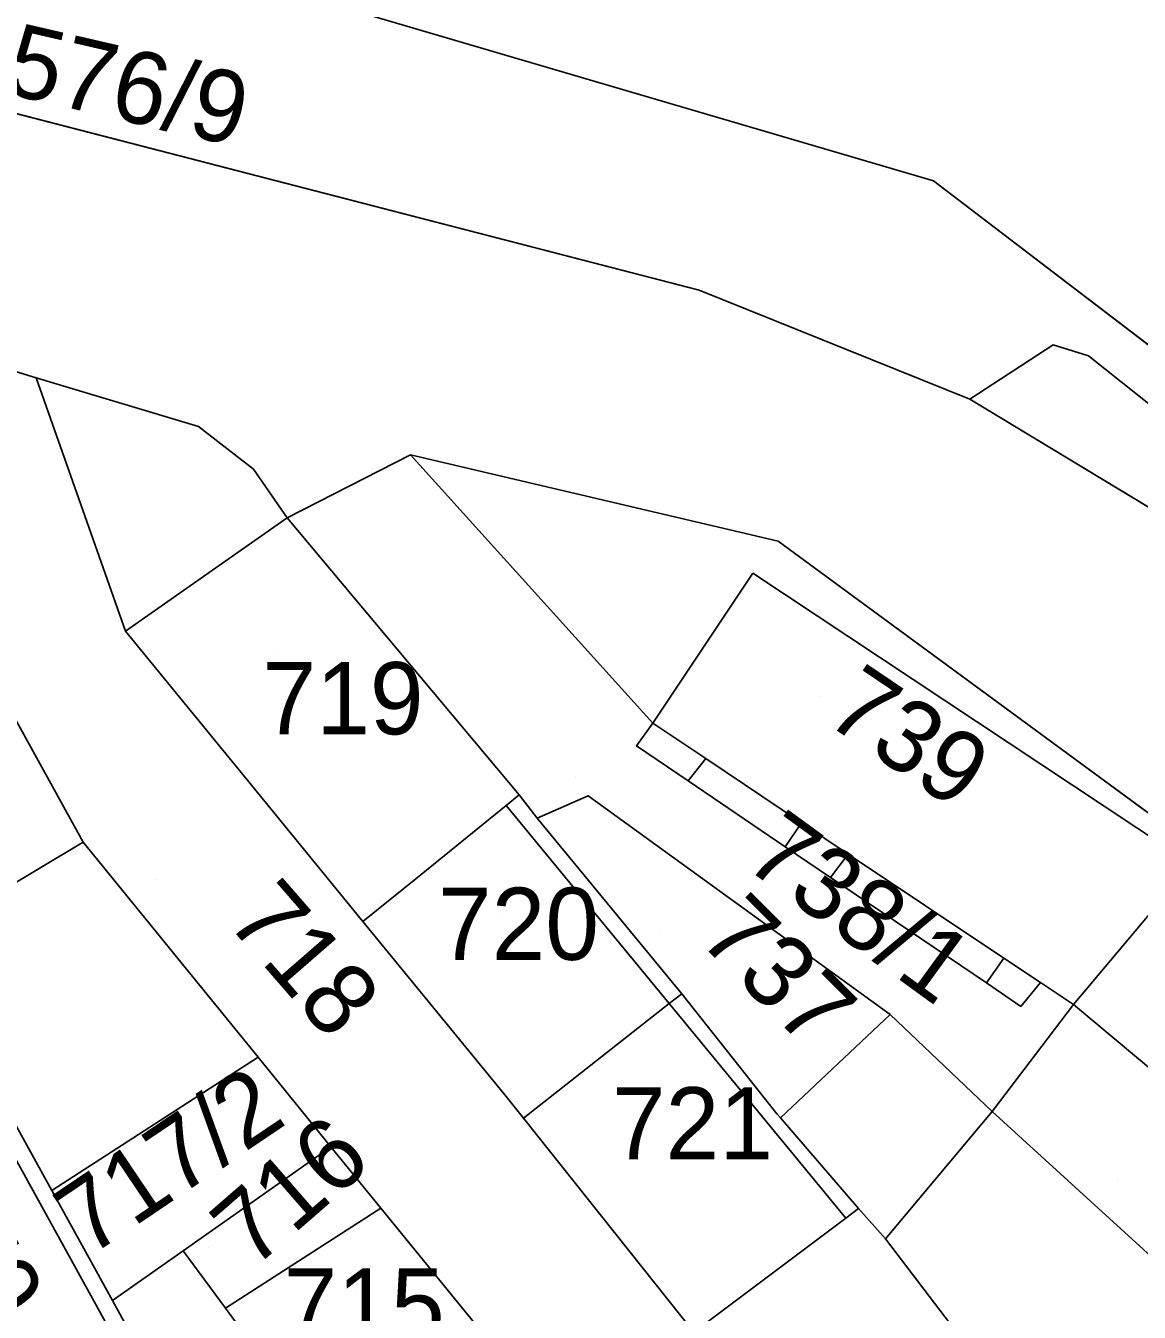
# Model space of a CAD drawing. Extents: x -263943 to -261149, y -1236934 to -1230686.
# Drawn here: x -262510.84 to -262479.98, y -1235394.91 to -1235359.25 of the extents above; entities that cross this region are included whole.
import ezdxf

# ---------------------------------------------------------------- set-up
doc = ezdxf.new("R2010")
doc.units = 0
for name, color, linetype in [('body_kn', 7, 'Continuous'), ('kladpar_druhypozemkov', 7, 'Continuous'), ('kladpar_hranice', 7, 'Continuous'), ('kladpar_parcelnecisla', 7, 'Continuous'), ('kladpar_plochy', 7, 'Continuous'), ('zappar_hrandruhpozemk', 7, 'Continuous')]:
    doc.layers.add(name, color=color, linetype=linetype)

msp = doc.modelspace()

# ---------------------------------------------------------------- linework, layer by layer
at = {"layer": 'body_kn'}
for p, q in [((-262485.69, -1235363.55), (-262485.69, -1235363.55)), ((-262492.18, -1235366.58), (-262492.18, -1235366.58)), ((-262482.37, -1235368.1), (-262482.37, -1235368.1)), ((-262481.39, -1235368.4), (-262481.39, -1235368.4)), ((-262510.56, -1235369.01), (-262510.56, -1235369.01)), ((-262510.56, -1235369.01), (-262510.56, -1235369.01)), ((-262484.68, -1235369.6), (-262484.68, -1235369.6)), ((-262484.68, -1235369.6), (-262484.68, -1235369.6)), ((-262506.06, -1235370.36), (-262506.06, -1235370.36)), ((-262500.18, -1235371.15), (-262500.18, -1235371.15)), ((-262504.53, -1235371.54), (-262504.53, -1235371.54)), ((-262503.6, -1235372.89), (-262503.6, -1235372.89)), ((-262503.6, -1235372.89), (-262503.6, -1235372.89)), ((-262489.99, -1235373.54), (-262489.99, -1235373.54)), ((-262490.69, -1235374.42), (-262490.69, -1235374.42)), ((-262508.08, -1235376.03), (-262508.08, -1235376.03)), ((-262493.47, -1235378.58), (-262493.47, -1235378.58)), ((-262493.47, -1235378.58), (-262493.47, -1235378.58)), ((-262493.92, -1235379.21), (-262493.92, -1235379.21)), ((-262492, -1235379.56), (-262492, -1235379.56)), ((-262504.79, -1235380.05), (-262504.79, -1235380.05)), ((-262492.49, -1235380.18), (-262492.49, -1235380.18)), ((-262492.49, -1235380.18), (-262492.49, -1235380.18)), ((-262497.17, -1235380.57), (-262497.17, -1235380.57)), ((-262497.17, -1235380.57), (-262497.17, -1235380.57)), ((-262495.26, -1235380.59), (-262495.26, -1235380.59)), ((-262497.53, -1235380.86), (-262497.53, -1235380.86)), ((-262497.53, -1235380.86), (-262497.53, -1235380.86)), ((-262496.67, -1235381.21), (-262496.67, -1235381.21)), ((-262489.35, -1235381.34), (-262489.35, -1235381.34)), ((-262509.25, -1235381.88), (-262509.25, -1235381.88)), ((-262489.8, -1235382.01), (-262489.8, -1235382.01)), ((-262489.8, -1235382.01), (-262489.8, -1235382.01)), ((-262488.05, -1235382.21), (-262488.05, -1235382.21)), ((-262500.03, -1235382.89), (-262500.03, -1235382.89)), ((-262488.54, -1235382.86), (-262488.54, -1235382.86)), ((-262488.54, -1235382.86), (-262488.54, -1235382.86)), ((-262501.5, -1235384.08), (-262501.5, -1235384.08)), ((-262483.74, -1235385.09), (-262483.74, -1235385.09)), ((-262484.22, -1235385.78), (-262484.22, -1235385.78)), ((-262484.22, -1235385.78), (-262484.22, -1235385.78)), ((-262482.72, -1235385.77), (-262482.72, -1235385.77)), ((-262492.66, -1235386.08), (-262492.66, -1235386.08)), ((-262492.66, -1235386.08), (-262492.66, -1235386.08)), ((-262493.01, -1235386.35), (-262493.01, -1235386.35)), ((-262493.01, -1235386.35), (-262493.01, -1235386.35)), ((-262486.89, -1235386.65), (-262486.89, -1235386.65)), ((-262483.27, -1235386.43), (-262483.27, -1235386.43)), ((-262481.81, -1235386.38), (-262481.81, -1235386.38)), ((-262481.81, -1235386.38), (-262481.81, -1235386.38)), ((-262504.4, -1235387.84), (-262504.4, -1235387.84)), ((-262504.4, -1235387.84), (-262504.4, -1235387.84)), ((-262497.57, -1235388.88), (-262497.57, -1235388.88)), ((-262497.05, -1235389.53), (-262497.05, -1235389.53)), ((-262490.03, -1235389.41), (-262490.03, -1235389.41)), ((-262489.93, -1235389.52), (-262489.93, -1235389.52)), ((-262489.93, -1235389.52), (-262489.93, -1235389.52)), ((-262484.06, -1235389.34), (-262484.06, -1235389.34)), ((-262502.39, -1235390.32), (-262502.39, -1235390.32)), ((-262510.12, -1235391.53), (-262510.12, -1235391.53)), ((-262510.12, -1235391.53), (-262510.12, -1235391.53)), ((-262501, -1235392.02), (-262501, -1235392.02)), ((-262487.77, -1235392.03), (-262487.77, -1235392.03)), ((-262487.77, -1235392.03), (-262487.77, -1235392.03)), ((-262488.12, -1235392.3), (-262488.12, -1235392.3)), ((-262487.02, -1235392.87), (-262487.02, -1235392.87)), ((-262506.48, -1235393.2), (-262506.48, -1235393.2)), ((-262506.48, -1235393.2), (-262506.48, -1235393.2)), ((-262508.44, -1235394.58), (-262508.44, -1235394.58)), ((-262508.44, -1235394.58), (-262508.44, -1235394.58)), ((-262505.31, -1235394.79), (-262505.31, -1235394.79)), ((-262505.31, -1235394.79), (-262505.31, -1235394.79))]:
    msp.add_line(p, q, dxfattribs=at)
at = {"layer": 'kladpar_druhypozemkov'}
for p, q in [((-262508.29, -1235360.29), (-262508.29, -1235360.29)), ((-262503.85, -1235376.55), (-262503.85, -1235376.55)), ((-262488.85, -1235377.83), (-262488.85, -1235377.83)), ((-262495.6, -1235380.08), (-262495.6, -1235380.08)), ((-262507.26, -1235382.9), (-262507.26, -1235382.9)), ((-262497.77, -1235383.86), (-262497.77, -1235383.86)), ((-262493.25, -1235384.33), (-262493.25, -1235384.33)), ((-262493.08, -1235389.24), (-262493.08, -1235389.24)), ((-262506.45, -1235389.76), (-262506.45, -1235389.76)), ((-262480.6, -1235391.23), (-262480.6, -1235391.23)), ((-262505.77, -1235393.11), (-262505.77, -1235393.11)), ((-262501.68, -1235394.37), (-262501.68, -1235394.37))]:
    msp.add_line(p, q, dxfattribs=at)
at = {"layer": 'kladpar_hranice'}
for points in [[(-262395.03, -1235450.14), (-262423.63, -1235423.11), (-262436.22, -1235407.42), (-262449.19, -1235391.42), (-262471.72, -1235374.22), (-262485.69, -1235363.55), (-262518.57, -1235353.89), (-262518.6, -1235353.56), (-262519.93, -1235347.59), (-262525.13, -1235332.75), (-262534.5, -1235316.26), (-262539.66, -1235305.8), (-262542.07, -1235301.69)], [(-262471.72, -1235374.22), (-262473.44, -1235374.61), (-262474.8, -1235376.29), (-262478.54, -1235373.32), (-262484.68, -1235369.6), (-262492.18, -1235366.58), (-262518.32, -1235359.83), (-262518.86, -1235358.75), (-262518.37, -1235355.88), (-262518.57, -1235353.89), (-262485.69, -1235363.55), (-262471.72, -1235374.22)], [(-262518.86, -1235358.75), (-262518.32, -1235359.83), (-262492.18, -1235366.58), (-262484.68, -1235369.6), (-262478.54, -1235373.32)], [(-262478.59, -1235381.91), (-262489.99, -1235373.54), (-262500.18, -1235371.15), (-262503.6, -1235372.89), (-262504.53, -1235371.54), (-262506.06, -1235370.36), (-262510.56, -1235369.01), (-262514.12, -1235367.92), (-262515.65, -1235366.4), (-262525.02, -1235364.84), (-262525.23, -1235364.81), (-262525.77, -1235364.71), (-262532.61, -1235363.38), (-262538.03, -1235363.56)], [(-262504.4, -1235387.84), (-262510.12, -1235391.53), (-262511.46, -1235389.1), (-262513.94, -1235384.68), (-262519.73, -1235374.38), (-262522.17, -1235370.05), (-262525.02, -1235364.84), (-262515.65, -1235366.4), (-262516.74, -1235367.01), (-262511.13, -1235377.14), (-262511.7, -1235377.45), (-262509.25, -1235381.88), (-262504.4, -1235387.84)], [(-262478.88, -1235424.54), (-262480.47, -1235421.95), (-262484.72, -1235415.05), (-262489.9, -1235406.87), (-262494.02, -1235400.6), (-262498.1, -1235395.58), (-262501, -1235392.02), (-262502.39, -1235390.32), (-262504.4, -1235387.84), (-262509.25, -1235381.88), (-262511.7, -1235377.45), (-262511.13, -1235377.14), (-262516.74, -1235367.01), (-262515.65, -1235366.4)], [(-262515.65, -1235366.4), (-262514.12, -1235367.92), (-262510.56, -1235369.01), (-262506.06, -1235370.36), (-262504.53, -1235371.54), (-262503.6, -1235372.89), (-262508.08, -1235376.03), (-262504.79, -1235380.05), (-262501.5, -1235384.08), (-262497.57, -1235388.88), (-262497.05, -1235389.53), (-262492.33, -1235395.46), (-262492.62, -1235395.68), (-262488.47, -1235401.67), (-262488.57, -1235401.74), (-262487.17, -1235403.59), (-262486.31, -1235404.73), (-262481.94, -1235410.5), (-262481.45, -1235410.12), (-262473.92, -1235420.24)], [(-262489.8, -1235382.01), (-262488.54, -1235382.86), (-262484.22, -1235385.78), (-262483.27, -1235386.43), (-262482.72, -1235385.77), (-262481.81, -1235386.38), (-262484.06, -1235389.34), (-262486.89, -1235386.65), (-262495.26, -1235380.59), (-262496.67, -1235381.21), (-262497.17, -1235380.57), (-262503.6, -1235372.89), (-262500.18, -1235371.15), (-262493.47, -1235378.58), (-262493.92, -1235379.21), (-262492.49, -1235380.18), (-262489.8, -1235382.01)], [(-262481.81, -1235386.38), (-262482.72, -1235385.77), (-262483.27, -1235386.43), (-262484.22, -1235385.78), (-262488.54, -1235382.86), (-262489.8, -1235382.01), (-262492.49, -1235380.18), (-262493.92, -1235379.21), (-262493.47, -1235378.58), (-262500.18, -1235371.15), (-262489.99, -1235373.54), (-262478.59, -1235381.91), (-262478.27, -1235382.17), (-262478.54, -1235382.49), (-262481.81, -1235386.38)], [(-262503.6, -1235372.89), (-262497.17, -1235380.57), (-262497.53, -1235380.86), (-262500.03, -1235382.89), (-262501.5, -1235384.08), (-262504.79, -1235380.05), (-262508.08, -1235376.03), (-262503.6, -1235372.89)], [(-262497.17, -1235380.57), (-262496.67, -1235381.21), (-262492.66, -1235386.08), (-262493.01, -1235386.35), (-262497.05, -1235389.53), (-262497.57, -1235388.88), (-262501.5, -1235384.08), (-262500.03, -1235382.89), (-262497.53, -1235380.86), (-262497.17, -1235380.57)], [(-262487.77, -1235392.03), (-262489.93, -1235389.52), (-262490.03, -1235389.41), (-262492.66, -1235386.08), (-262496.67, -1235381.21), (-262495.26, -1235380.59), (-262486.89, -1235386.65), (-262484.06, -1235389.34), (-262487.02, -1235392.87), (-262487.77, -1235392.03)], [(-262481.81, -1235386.38), (-262478.54, -1235382.49), (-262478.27, -1235382.17), (-262478.59, -1235381.91), (-262478.21, -1235381.53), (-262466.51, -1235391.17), (-262466.86, -1235391.6), (-262470.43, -1235395.89), (-262481.81, -1235386.38)], [(-262492.66, -1235386.08), (-262490.03, -1235389.41), (-262489.93, -1235389.52), (-262487.77, -1235392.03), (-262488.12, -1235392.3), (-262492.33, -1235395.46), (-262497.05, -1235389.53), (-262493.01, -1235386.35), (-262492.66, -1235386.08)], [(-262469.18, -1235398), (-262468.6, -1235397.32), (-262464.33, -1235400.66), (-262461.32, -1235403), (-262461.82, -1235403.67), (-262460.5, -1235404.7), (-262459.97, -1235404.06), (-262454.76, -1235408.12), (-262455.66, -1235409.19), (-262452.77, -1235411.95), (-262453.81, -1235414.8), (-262461.48, -1235407.92), (-262466.84, -1235404.12), (-262472.75, -1235398.92), (-262475.46, -1235397.18), (-262484.06, -1235389.34), (-262481.81, -1235386.38), (-262470.43, -1235395.89), (-262469.85, -1235396.35), (-262470.31, -1235397.04), (-262469.18, -1235398)], [(-262510.12, -1235391.53), (-262504.4, -1235387.84), (-262502.39, -1235390.32), (-262506.48, -1235393.2), (-262508.44, -1235394.58), (-262510.12, -1235391.53)], [(-262508.44, -1235394.58), (-262507.85, -1235395.66), (-262508.24, -1235395.89), (-262513.25, -1235398.84), (-262516.94, -1235392.22), (-262511.86, -1235389.33), (-262511.46, -1235389.1), (-262510.12, -1235391.53), (-262508.44, -1235394.58)], [(-262483.27, -1235397.79), (-262487.02, -1235392.87), (-262484.06, -1235389.34), (-262475.46, -1235397.18), (-262472.75, -1235398.92), (-262478.23, -1235404.67), (-262483.27, -1235397.79)], [(-262506.48, -1235393.2), (-262502.39, -1235390.32), (-262501, -1235392.02), (-262505.31, -1235394.79), (-262506.48, -1235393.2)], [(-262505.31, -1235394.79), (-262501, -1235392.02), (-262498.1, -1235395.58), (-262502.77, -1235398.26), (-262505.31, -1235394.79)], [(-262487.77, -1235392.03), (-262487.02, -1235392.87), (-262483.27, -1235397.79), (-262483.72, -1235398.12), (-262487.99, -1235401.31), (-262488.47, -1235401.67), (-262492.62, -1235395.68), (-262492.33, -1235395.46), (-262488.12, -1235392.3), (-262487.77, -1235392.03)], [(-262501.76, -1235406.7), (-262503.21, -1235404.06), (-262505.54, -1235399.84), (-262507.54, -1235396.22), (-262507.85, -1235395.66), (-262508.44, -1235394.58), (-262506.48, -1235393.2), (-262505.31, -1235394.79), (-262502.77, -1235398.26), (-262498.1, -1235395.58), (-262494.02, -1235400.6), (-262501.2, -1235406.26), (-262501.76, -1235406.7)]]:
    msp.add_lwpolyline(points, dxfattribs=at)
at = {"layer": 'kladpar_plochy'}
for p, q in [((-262485.69, -1235363.55), (-262518.57, -1235353.89)), ((-262518.32, -1235359.83), (-262492.18, -1235366.58)), ((-262471.72, -1235374.22), (-262485.69, -1235363.55)), ((-262492.18, -1235366.58), (-262484.68, -1235369.6)), ((-262510.56, -1235369.01), (-262514.12, -1235367.92)), ((-262506.06, -1235370.36), (-262510.56, -1235369.01)), ((-262484.68, -1235369.6), (-262478.54, -1235373.32)), ((-262504.53, -1235371.54), (-262506.06, -1235370.36)), ((-262500.18, -1235371.15), (-262503.6, -1235372.89)), ((-262489.99, -1235373.54), (-262500.18, -1235371.15)), ((-262503.6, -1235372.89), (-262504.53, -1235371.54)), ((-262478.59, -1235381.91), (-262489.99, -1235373.54))]:
    msp.add_line(p, q, dxfattribs=at)
for points in [[(-262471.72, -1235374.22), (-262473.44, -1235374.61), (-262474.8, -1235376.29), (-262478.54, -1235373.32), (-262484.68, -1235369.6), (-262492.18, -1235366.58), (-262518.32, -1235359.83), (-262518.86, -1235358.75), (-262518.37, -1235355.88), (-262518.57, -1235353.89), (-262485.69, -1235363.55)], [(-262504.4, -1235387.84), (-262510.12, -1235391.53), (-262511.46, -1235389.1), (-262513.94, -1235384.68), (-262519.73, -1235374.38), (-262522.17, -1235370.05), (-262525.02, -1235364.84), (-262515.65, -1235366.4), (-262516.74, -1235367.01), (-262511.13, -1235377.14), (-262511.7, -1235377.45), (-262509.25, -1235381.88)], [(-262489.8, -1235382.01), (-262488.54, -1235382.86), (-262484.22, -1235385.78), (-262483.27, -1235386.43), (-262482.72, -1235385.77), (-262481.81, -1235386.38), (-262484.06, -1235389.34), (-262486.89, -1235386.65), (-262495.26, -1235380.59), (-262496.67, -1235381.21), (-262497.17, -1235380.57), (-262503.6, -1235372.89), (-262500.18, -1235371.15), (-262493.47, -1235378.58), (-262493.92, -1235379.21), (-262492.49, -1235380.18)], [(-262481.81, -1235386.38), (-262482.72, -1235385.77), (-262483.27, -1235386.43), (-262484.22, -1235385.78), (-262488.54, -1235382.86), (-262489.8, -1235382.01), (-262492.49, -1235380.18), (-262493.92, -1235379.21), (-262493.47, -1235378.58), (-262500.18, -1235371.15), (-262489.99, -1235373.54), (-262478.59, -1235381.91), (-262478.27, -1235382.17), (-262478.54, -1235382.49)], [(-262503.6, -1235372.89), (-262497.17, -1235380.57), (-262497.53, -1235380.86), (-262500.03, -1235382.89), (-262501.5, -1235384.08), (-262504.79, -1235380.05), (-262508.08, -1235376.03)], [(-262497.17, -1235380.57), (-262496.67, -1235381.21), (-262492.66, -1235386.08), (-262493.01, -1235386.35), (-262497.05, -1235389.53), (-262497.57, -1235388.88), (-262501.5, -1235384.08), (-262500.03, -1235382.89), (-262497.53, -1235380.86)], [(-262487.77, -1235392.03), (-262489.93, -1235389.52), (-262490.03, -1235389.41), (-262492.66, -1235386.08), (-262496.67, -1235381.21), (-262495.26, -1235380.59), (-262486.89, -1235386.65), (-262484.06, -1235389.34), (-262487.02, -1235392.87)], [(-262481.81, -1235386.38), (-262478.54, -1235382.49), (-262478.27, -1235382.17), (-262478.59, -1235381.91), (-262478.21, -1235381.53), (-262466.51, -1235391.17), (-262466.86, -1235391.6), (-262470.43, -1235395.89)], [(-262492.66, -1235386.08), (-262490.03, -1235389.41), (-262489.93, -1235389.52), (-262487.77, -1235392.03), (-262488.12, -1235392.3), (-262492.33, -1235395.46), (-262497.05, -1235389.53), (-262493.01, -1235386.35)], [(-262469.18, -1235398), (-262468.6, -1235397.32), (-262464.33, -1235400.66), (-262461.32, -1235403), (-262461.82, -1235403.67), (-262460.5, -1235404.7), (-262459.97, -1235404.06), (-262454.76, -1235408.12), (-262455.66, -1235409.19), (-262452.77, -1235411.95), (-262453.81, -1235414.8), (-262461.48, -1235407.92), (-262466.84, -1235404.12), (-262472.75, -1235398.92), (-262475.46, -1235397.18), (-262484.06, -1235389.34), (-262481.81, -1235386.38), (-262470.43, -1235395.89), (-262469.85, -1235396.35), (-262470.31, -1235397.04)], [(-262510.12, -1235391.53), (-262504.4, -1235387.84), (-262502.39, -1235390.32), (-262506.48, -1235393.2), (-262508.44, -1235394.58)], [(-262508.44, -1235394.58), (-262507.85, -1235395.66), (-262508.24, -1235395.89), (-262513.25, -1235398.84), (-262516.94, -1235392.22), (-262511.86, -1235389.33), (-262511.46, -1235389.1), (-262510.12, -1235391.53)], [(-262483.27, -1235397.79), (-262487.02, -1235392.87), (-262484.06, -1235389.34), (-262475.46, -1235397.18), (-262472.75, -1235398.92), (-262478.23, -1235404.67)], [(-262506.48, -1235393.2), (-262502.39, -1235390.32), (-262501, -1235392.02), (-262505.31, -1235394.79)], [(-262505.31, -1235394.79), (-262501, -1235392.02), (-262498.1, -1235395.58), (-262502.77, -1235398.26)], [(-262487.77, -1235392.03), (-262487.02, -1235392.87), (-262483.27, -1235397.79), (-262483.72, -1235398.12), (-262487.99, -1235401.31), (-262488.47, -1235401.67), (-262492.62, -1235395.68), (-262492.33, -1235395.46), (-262488.12, -1235392.3)], [(-262501.76, -1235406.7), (-262503.21, -1235404.06), (-262505.54, -1235399.84), (-262507.54, -1235396.22), (-262507.85, -1235395.66), (-262508.44, -1235394.58), (-262506.48, -1235393.2), (-262505.31, -1235394.79), (-262502.77, -1235398.26), (-262498.1, -1235395.58), (-262494.02, -1235400.6), (-262501.2, -1235406.26)]]:
    msp.add_lwpolyline(points, close=True, dxfattribs=at)
msp.add_lwpolyline([(-262498.1, -1235395.58), (-262501, -1235392.02), (-262502.39, -1235390.32), (-262504.4, -1235387.84), (-262509.25, -1235381.88), (-262511.7, -1235377.45), (-262511.13, -1235377.14), (-262516.74, -1235367.01), (-262515.65, -1235366.4), (-262514.12, -1235367.92), (-262510.56, -1235369.01), (-262506.06, -1235370.36), (-262504.53, -1235371.54), (-262503.6, -1235372.89), (-262508.08, -1235376.03), (-262504.79, -1235380.05), (-262501.5, -1235384.08), (-262497.57, -1235388.88), (-262497.05, -1235389.53), (-262492.33, -1235395.46)], dxfattribs=at)
at = {"layer": 'zappar_hrandruhpozemk'}
for p, q in [((-262481.39, -1235368.4), (-262477.91, -1235371.18)), ((-262510.56, -1235369.01), (-262508.08, -1235376.03)), ((-262490.69, -1235374.42), (-262493.47, -1235378.58)), ((-262478.54, -1235382.49), (-262490.69, -1235374.42)), ((-262492.49, -1235380.18), (-262492, -1235379.56)), ((-262497.53, -1235380.86), (-262493.01, -1235386.35)), ((-262489.8, -1235382.01), (-262489.35, -1235381.34)), ((-262513.7, -1235384.53), (-262509.25, -1235381.88)), ((-262488.54, -1235382.86), (-262488.05, -1235382.21)), ((-262484.22, -1235385.78), (-262483.74, -1235385.09)), ((-262493.01, -1235386.35), (-262488.12, -1235392.3)), ((-262489.93, -1235389.52), (-262486.89, -1235386.65)), ((-262508.24, -1235395.89), (-262511.86, -1235389.33))]:
    msp.add_line(p, q, dxfattribs=at)
for points in [[(-262484.68, -1235369.6), (-262482.37, -1235368.1), (-262481.39, -1235368.4)], [(-262493.47, -1235378.58), (-262492, -1235379.56), (-262489.35, -1235381.34), (-262488.05, -1235382.21), (-262483.74, -1235385.09), (-262482.72, -1235385.77)]]:
    msp.add_lwpolyline(points, dxfattribs=at)

# ---------------------------------------------------------------- texts
at = {"layer": 'kladpar_parcelnecisla'}
for s, rotation, p in [('1576/9', 347, (-262512.939, -1235360.774)), ('739', 326, (-262488.761, -1235378.523)), ('738/1', 324, (-262491.004, -1235382.515)), ('718', 311, (-262505.329, -1235384.068)), ('737', 315, (-262492.258, -1235384.576)), ('717/2', 34, (-262509.103, -1235393.394)), ('716', 41, (-262504.564, -1235393.743)), ('704', 299, (-262513.432, -1235392.788))]:
    msp.add_text(s, height=2, rotation=rotation, dxfattribs=at).set_placement(p)
for s, p in [('719', (-262504.282, -1235378.89)), ('720', (-262499.42, -1235385.14)), ('721', (-262494.599, -1235390.67)), ('715', (-262503.697, -1235395.69))]:
    msp.add_text(s, height=2, dxfattribs=at).set_placement(p)

doc.saveas('drawing.dxf')
